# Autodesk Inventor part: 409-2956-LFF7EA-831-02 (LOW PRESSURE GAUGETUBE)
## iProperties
Created: 2010-09
Part Number: 409-2956-LFF7EA-831-02 (LOW PRESSURE GAUGETUBE)
Material: 3/8"OD TUBE - SS
Document SubType Name: Modeling
Designer: S. Boerckel
Engineer: Steve Boerckel
Mass: 166.544 g
Surface Area: 342.312 cm^2
Volume: 20.6119 cm^3
Density: 8.08 g/cm^3
Description: LOW PRESSURE GAUGE TUBE
Author: S. Boerckel
Revision Number: 0
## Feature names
1. Sweep1
